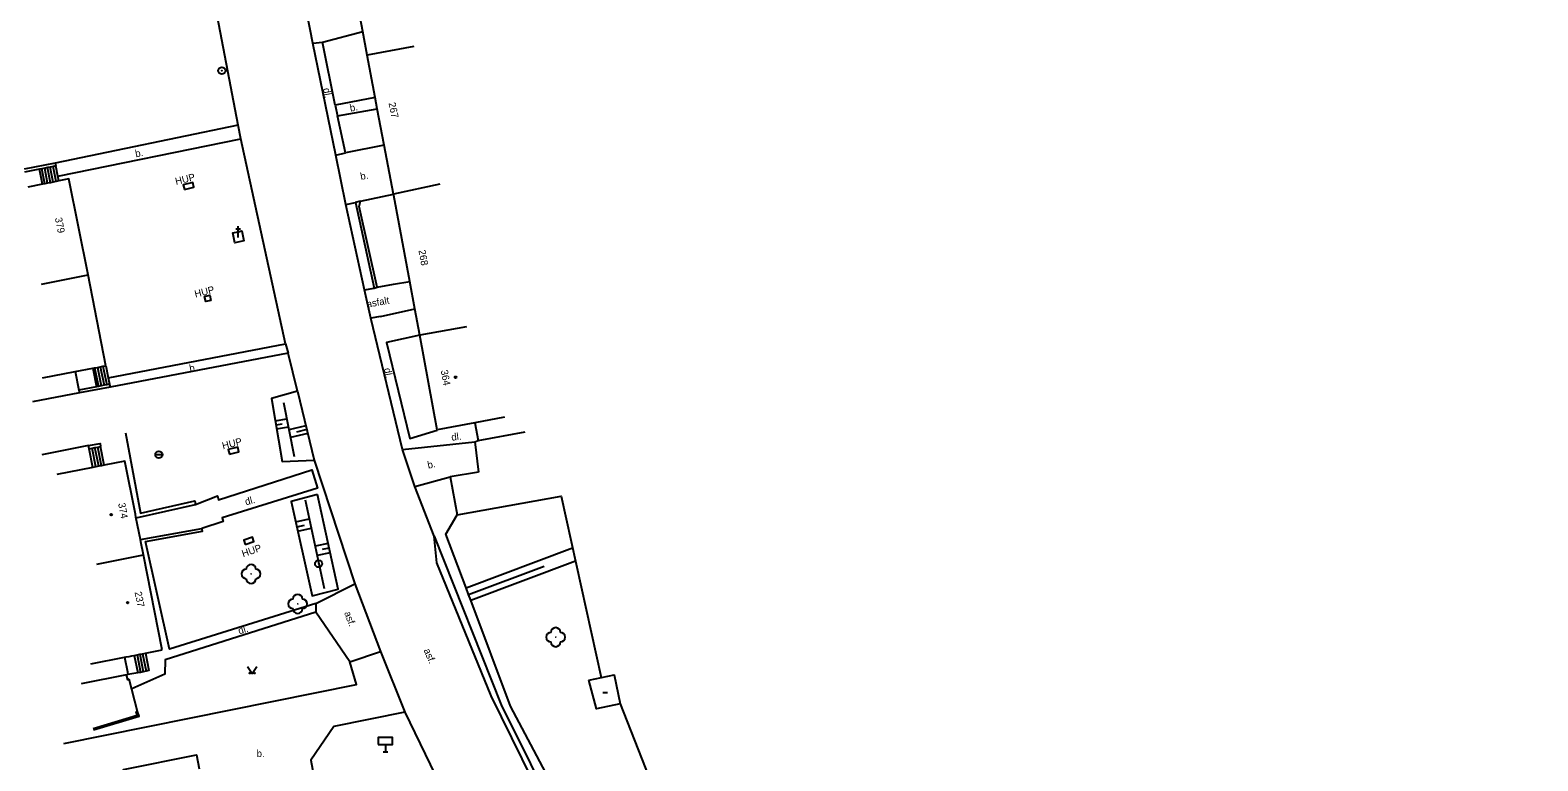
# Model space of a CAD drawing. Extents: x -582162 to -561283, y -1187583 to -1183539.
# Drawn here: x -578179.7 to -578021.2, y -1186545 to -1186468.2 of the extents above; entities that cross this region are included whole.
import ezdxf

# ---------------------------------------------------------------- set-up
doc = ezdxf.new("R2010")
doc.units = 0
for name, color, linetype in [('Vrstva 1', 7, 'Continuous'), ('Vrstva 10', 7, 'Continuous'), ('Vrstva 11', 7, 'Continuous'), ('Vrstva 12', 7, 'Continuous'), ('Vrstva 14', 7, 'Continuous'), ('Vrstva 3', 7, 'Continuous'), ('Vrstva 4', 7, 'Continuous'), ('Vrstva 6', 7, 'Continuous'), ('Vrstva 8', 7, 'Continuous'), ('Vrstva 9', 7, 'Continuous')]:
    doc.layers.add(name, color=color, linetype=linetype)

# ---------------------------------------------------------------- blocks, each defined once
blk = doc.blocks.new('1.079')
at = {"layer": 'Vrstva 1'}
for radius in [0.75, 0.001]:
    blk.add_circle((0, -0.001), radius, dxfattribs=at)
blk = doc.blocks.new('3.130')
at = {"layer": 'Vrstva 1'}
blk.add_circle((0, 0), 0.001, dxfattribs=at)
for centre, start, end in [((-1, 0), 90, 270), ((0, 1), 0, 180), ((1, 0), 270, 90), ((0, -1), 180, 360)]:
    blk.add_arc(centre, 1, start, end, dxfattribs=at)
blk = doc.blocks.new('3.140')
at = {"layer": 'Vrstva 1'}
blk.add_lwpolyline([(-1, 1.5), (0, 0), (1, 1.5)], dxfattribs=at)
for centre in [(-0.5, 0.1), (0.5, 0.1)]:
    blk.add_circle(centre, 0.1, dxfattribs=at)
blk = doc.blocks.new('4.020')
at = {"layer": 'Vrstva 1'}
blk.add_circle((0, 0), 0.175, dxfattribs=at)
blk = doc.blocks.new('4.030')
at = {"layer": 'Vrstva 1'}
blk.add_line((-0.5, 0), (0.5, 0), dxfattribs=at)
blk = doc.blocks.new('5.261')
at = {"layer": 'Vrstva 1'}
for p, q in [((-0.5, 0), (0.5, 0)), ((0, 1.5), (0, 0))]:
    blk.add_line(p, q, dxfattribs=at)
blk.add_lwpolyline([(-1.5, 1.5), (1.5, 1.5), (1.5, 3), (-1.5, 3)], close=True, dxfattribs=at)
blk = doc.blocks.new('8.110')
at = {"layer": 'Vrstva 1'}
blk.add_line((-0.75, 0), (0.75, 0), dxfattribs=at)
blk.add_circle((0, 0), 0.75, dxfattribs=at)

msp = doc.modelspace()

# ---------------------------------------------------------------- linework, layer by layer
at = {"layer": 'Vrstva 10'}
for points in [[(-578157.78, -1186478.2), (-578162.64, -1186452.9)], [(-578149.96, -1186469.58), (-578150.56, -1186466.51)], [(-578148.93, -1186469.45), (-578144.7, -1186468.33)], [(-578149.96, -1186469.58), (-578148.93, -1186469.45)], [(-578147.54, -1186481.33), (-578149.96, -1186469.58)], [(-578147.59, -1186476.07), (-578148.93, -1186469.45)], [(-578143.39, -1186475.29), (-578147.59, -1186476.07)], [(-578147.59, -1186476.07), (-578147.35, -1186477.22)], [(-578147.35, -1186477.22), (-578143.17, -1186476.47)], [(-578157.78, -1186478.2), (-578177.01, -1186482.17)], [(-578157.5, -1186479.63), (-578157.78, -1186478.2)], [(-578146.51, -1186481.11), (-578147.35, -1186477.22)], [(-578176.73, -1186483.54), (-578157.5, -1186479.63)], [(-578152.83, -1186501.19), (-578157.5, -1186479.63)], [(-578142.45, -1186480.29), (-578146.51, -1186481.11)], [(-578147.54, -1186481.33), (-578146.51, -1186481.11)], [(-578146.47, -1186486.53), (-578147.54, -1186481.33)], [(-578177.01, -1186482.17), (-578180.29, -1186482.83)], [(-578178.66, -1186482.81), (-578180.23, -1186483.12)], [(-578178.42, -1186482.77), (-578178.66, -1186482.81)], [(-578178.34, -1186484.4), (-578178.66, -1186482.81)], [(-578178.12, -1186482.71), (-578178.42, -1186482.77)], [(-578178.1, -1186484.35), (-578178.42, -1186482.77)], [(-578177.83, -1186482.65), (-578178.12, -1186482.71)], [(-578177.81, -1186484.3), (-578178.12, -1186482.71)], [(-578177.54, -1186482.59), (-578177.83, -1186482.65)], [(-578177.51, -1186484.24), (-578177.83, -1186482.65)], [(-578177.24, -1186482.53), (-578177.54, -1186482.59)], [(-578177.22, -1186484.18), (-578177.54, -1186482.59)], [(-578176.95, -1186482.47), (-578177.24, -1186482.53)], [(-578176.92, -1186484.12), (-578177.24, -1186482.53)], [(-578177.01, -1186482.17), (-578176.95, -1186482.47)], [(-578176.73, -1186483.54), (-578176.95, -1186482.47)], [(-578176.63, -1186484.06), (-578176.73, -1186483.54)], [(-578163.44, -1186484.96), (-578162.44, -1186484.71), (-578162.56, -1186484.22), (-578163.56, -1186484.48), (-578163.44, -1186484.96)], [(-578146.47, -1186486.53), (-578145.46, -1186486.33)], [(-578144.52, -1186495.49), (-578146.47, -1186486.53)], [(-578144.93, -1186486.17), (-578145.46, -1186486.33)], [(-578145.46, -1186486.33), (-578143.5, -1186495.32)], [(-578157.79, -1186489.39), (-578157.4, -1186489.31), (-578157.19, -1186490.35), (-578158.15, -1186490.55), (-578158.36, -1186489.5), (-578157.79, -1186489.39)], [(-578158.04, -1186489.09), (-578157.79, -1186489.09)], [(-578157.79, -1186489.09), (-578157.79, -1186488.8)], [(-578157.79, -1186489.39), (-578157.79, -1186489.09)], [(-578157.79, -1186489.09), (-578157.55, -1186489.09)], [(-578157.79, -1186490.01), (-578157.79, -1186489.39)], [(-578160.66, -1186496.62), (-578161.2, -1186496.73), (-578161.32, -1186496.19), (-578160.78, -1186496.07), (-578160.66, -1186496.62)], [(-578144.52, -1186495.49), (-578143.5, -1186495.32)], [(-578143.87, -1186498.48), (-578144.52, -1186495.49)], [(-578143.5, -1186495.32), (-578143.2, -1186495.21)], [(-578141.47, -1186494.92), (-578139.77, -1186494.63)], [(-578142.83, -1186498.29), (-578139.24, -1186497.49)], [(-578142.83, -1186498.29), (-578143.87, -1186498.48)], [(-578001.12, -1186645.68), (-578034.13, -1186631.61), (-578060.86, -1186618.74), (-578080.51, -1186605.65), (-578096.31, -1186591.68), (-578110.71, -1186574.72), (-578121.4, -1186558.13), (-578131.21, -1186538.19), (-578136.91, -1186524.22), (-578137.19, -1186521.4), (-578139.24, -1186516.18), (-578140.52, -1186512.3), (-578143.87, -1186498.48)], [(-578138.72, -1186500.28), (-578142.2, -1186501.05), (-578139.77, -1186511.12), (-578136.88, -1186510.27)], [(-578171.44, -1186504.75), (-578152.83, -1186501.19)], [(-578152.54, -1186502.17), (-578171.24, -1186505.72)], [(-578152.83, -1186501.19), (-578152.54, -1186502.17)], [(-578151.56, -1186506.14), (-578152.54, -1186502.17)], [(-578173.08, -1186503.75), (-578172.68, -1186505.69)], [(-578172.88, -1186503.71), (-578172.48, -1186505.65)], [(-578172.59, -1186503.66), (-578172.19, -1186505.6)], [(-578172.29, -1186503.6), (-578171.89, -1186505.54)], [(-578172, -1186503.54), (-578171.6, -1186505.48)], [(-578171.71, -1186503.48), (-578171.44, -1186504.75)], [(-578172.68, -1186505.69), (-578174.54, -1186506.05)], [(-578172.48, -1186505.65), (-578172.68, -1186505.69)], [(-578172.19, -1186505.6), (-578172.48, -1186505.65)], [(-578171.89, -1186505.54), (-578172.19, -1186505.6)], [(-578171.6, -1186505.48), (-578171.89, -1186505.54)], [(-578171.3, -1186505.42), (-578171.6, -1186505.48)], [(-578171.44, -1186504.75), (-578171.3, -1186505.42)], [(-578171.3, -1186505.42), (-578171.24, -1186505.72)], [(-578171.24, -1186505.72), (-578174.48, -1186506.34)], [(-578151.56, -1186506.14), (-578149.82, -1186513.4), (-578145.54, -1186526.43), (-578142.83, -1186533.53), (-578140.28, -1186539.92), (-578128.02, -1186565.25), (-578116.68, -1186581.84), (-578105.73, -1186594.33), (-578094.04, -1186605.6), (-578079.84, -1186616.52), (-578063.76, -1186626.62), (-578051.68, -1186633.11), (-578004.55, -1186654.1)], [(-578173.52, -1186511.88), (-578172.31, -1186511.65), (-578172.25, -1186511.97)], [(-578172.84, -1186512.09), (-578172.54, -1186512.03)], [(-578172.54, -1186512.03), (-578172.25, -1186511.97)], [(-578172.16, -1186513.99), (-578172.54, -1186512.03)], [(-578171.86, -1186513.93), (-578172.25, -1186511.97)], [(-578169.63, -1186510.54), (-578168.04, -1186518.98), (-578162.35, -1186517.69), (-578162.27, -1186518.07)], [(-578158.71, -1186512.77), (-578157.72, -1186512.52), (-578157.84, -1186512.04), (-578158.84, -1186512.29), (-578158.71, -1186512.77)], [(-578140.52, -1186512.3), (-578132.92, -1186511.47), (-578132.57, -1186511.35)], [(-578173.45, -1186512.21), (-578173.13, -1186512.15)], [(-578173.13, -1186512.15), (-578172.84, -1186512.09)], [(-578172.74, -1186514.11), (-578173.13, -1186512.15)], [(-578172.45, -1186514.05), (-578172.84, -1186512.09)], [(-578162.27, -1186518.07), (-578159.98, -1186517.16), (-578159.86, -1186517.57), (-578150.06, -1186514.44), (-578149.46, -1186516.35), (-578159.48, -1186519.47), (-578159.36, -1186519.87), (-578161.62, -1186520.58)], [(-578139.24, -1186516.18), (-578135.52, -1186515.16)], [(-578168.51, -1186519.49), (-578162.27, -1186518.07)], [(-578168.07, -1186521.74), (-578161.62, -1186520.58)], [(-578167.53, -1186521.96), (-578161.53, -1186520.88), (-578161.62, -1186520.58)], [(-578157.05, -1186522.27), (-578156.13, -1186521.95), (-578156.28, -1186521.5), (-578157.21, -1186521.81), (-578157.05, -1186522.27)], [(-578149.63, -1186528.47), (-578165, -1186533.29), (-578167.53, -1186521.96)], [(-578149.63, -1186528.47), (-578145.54, -1186526.43)], [(-578149.62, -1186529.4), (-578165.47, -1186534.39), (-578165.49, -1186535.9), (-578168.98, -1186537.44)], [(-578149.63, -1186528.47), (-578149.62, -1186529.4)], [(-578146.06, -1186534.62), (-578149.62, -1186529.4)], [(-578146.06, -1186534.62), (-578142.83, -1186533.53)], [(-578176.11, -1186543.19), (-578145.37, -1186536.98), (-578146.06, -1186534.62)], [(-578169.24, -1186536.45), (-578169.38, -1186536.49), (-578169.52, -1186535.97)], [(-578168.36, -1186539.83), (-578169.24, -1186536.45)], [(-578140.28, -1186539.92), (-578147.73, -1186541.4), (-578150.16, -1186544.94), (-578148.15, -1186555.77), (-578150.75, -1186556.41), (-578154.16, -1186557.14)], [(-578169.55, -1186547.43), (-578169.85, -1186545.94), (-578162.18, -1186544.38), (-578161.88, -1186545.86)]]:
    msp.add_lwpolyline(points, dxfattribs=at)
at = {"layer": 'Vrstva 12'}
for points in [[(-578153.89, -1186509.28), (-578152.69, -1186509.08)], [(-578153.81, -1186509.71), (-578153.17, -1186509.6)], [(-578153.75, -1186510.11), (-578152.52, -1186509.9)], [(-578150.69, -1186509.79), (-578152.46, -1186510.21)], [(-578150.59, -1186510.2), (-578151.68, -1186510.47)], [(-578150.49, -1186510.59), (-578152.3, -1186511.02)], [(-578151.75, -1186519.9), (-578150.33, -1186519.58)], [(-578151.63, -1186520.43), (-578150.82, -1186520.25)], [(-578151.53, -1186520.87), (-578150.12, -1186520.55)], [(-578148.33, -1186522.17), (-578149.7, -1186522.47)], [(-578148.12, -1186523.14), (-578149.49, -1186523.44)], [(-578148.23, -1186522.65), (-578148.98, -1186522.82)], [(-578133.85, -1186526.84), (-578122.66, -1186522.62)], [(-578133.58, -1186527.54), (-578125.64, -1186524.55)], [(-578133.36, -1186528.14), (-578122.36, -1186523.99)]]:
    msp.add_lwpolyline(points, dxfattribs=at)
at = {"layer": 'Vrstva 4'}
for points in [[(-578144.7, -1186468.33), (-578145.21, -1186465.59)], [(-578144.23, -1186470.84), (-578144.7, -1186468.33)], [(-578139.32, -1186469.92), (-578144.23, -1186470.84)], [(-578143.39, -1186475.29), (-578144.23, -1186470.84)], [(-578143.17, -1186476.47), (-578143.39, -1186475.29)], [(-578142.45, -1186480.29), (-578143.17, -1186476.47)], [(-578141.48, -1186485.45), (-578142.45, -1186480.29)], [(-578178.34, -1186484.4), (-578179.91, -1186484.72)], [(-578178.1, -1186484.35), (-578178.34, -1186484.4)], [(-578177.81, -1186484.3), (-578178.1, -1186484.35)], [(-578177.51, -1186484.24), (-578177.81, -1186484.3)], [(-578177.22, -1186484.18), (-578177.51, -1186484.24)], [(-578176.92, -1186484.12), (-578177.22, -1186484.18)], [(-578176.63, -1186484.06), (-578176.92, -1186484.12)], [(-578173.56, -1186493.93), (-578175.58, -1186483.85), (-578176.63, -1186484.06)], [(-578136.59, -1186484.4), (-578141.48, -1186485.45)], [(-578141.45, -1186485.59), (-578141.48, -1186485.45)], [(-578139.77, -1186494.63), (-578141.45, -1186485.59)], [(-578178.46, -1186494.91), (-578173.56, -1186493.93)], [(-578171.71, -1186503.48), (-578173.56, -1186493.93)], [(-578139.24, -1186497.49), (-578139.77, -1186494.63)], [(-578138.72, -1186500.28), (-578139.24, -1186497.49)], [(-578133.8, -1186499.38), (-578138.72, -1186500.28)], [(-578136.89, -1186510.21), (-578138.72, -1186500.28)], [(-578178.37, -1186504.77), (-578174.92, -1186504.1)], [(-578174.92, -1186504.1), (-578173.08, -1186503.75)], [(-578174.92, -1186504.1), (-578174.54, -1186506.05)], [(-578173.08, -1186503.75), (-578172.88, -1186503.71)], [(-578172.88, -1186503.71), (-578172.59, -1186503.66)], [(-578172.59, -1186503.66), (-578172.29, -1186503.6)], [(-578172.29, -1186503.6), (-578172, -1186503.54)], [(-578172, -1186503.54), (-578171.71, -1186503.48)], [(-578174.48, -1186506.34), (-578179.39, -1186507.29)], [(-578174.54, -1186506.05), (-578174.48, -1186506.34)], [(-578132.91, -1186509.47), (-578136.89, -1186510.21)], [(-578129.8, -1186508.9), (-578132.91, -1186509.47)], [(-578132.91, -1186509.47), (-578132.57, -1186511.35)], [(-578132.57, -1186511.35), (-578127.65, -1186510.44)], [(-578173.52, -1186511.88), (-578178.42, -1186512.85)], [(-578173.45, -1186512.21), (-578173.52, -1186511.88)], [(-578173.07, -1186514.17), (-578173.45, -1186512.21)], [(-578168.59, -1186519.09), (-578169.69, -1186513.5), (-578171.86, -1186513.93)], [(-578173.07, -1186514.17), (-578176.85, -1186514.92)], [(-578172.74, -1186514.11), (-578173.07, -1186514.17)], [(-578172.45, -1186514.05), (-578172.74, -1186514.11)], [(-578172.16, -1186513.99), (-578172.45, -1186514.05)], [(-578171.86, -1186513.93), (-578172.16, -1186513.99)], [(-578168.53, -1186519.39), (-578168.59, -1186519.09)], [(-578168.07, -1186521.74), (-578168.53, -1186519.39)], [(-578168.02, -1186521.98), (-578168.07, -1186521.74)], [(-578167.75, -1186523.36), (-578168.02, -1186521.98)], [(-578172.65, -1186524.33), (-578167.75, -1186523.36)], [(-578165.78, -1186533.35), (-578167.75, -1186523.36)], [(-578173.26, -1186534.83), (-578169.73, -1186534.13)], [(-578169.73, -1186534.13), (-578169.55, -1186534.1)], [(-578169.73, -1186534.13), (-578169.43, -1186535.65)], [(-578169.55, -1186534.1), (-578169.26, -1186534.04)], [(-578169.26, -1186534.04), (-578168.96, -1186533.98)], [(-578168.96, -1186533.98), (-578168.71, -1186533.94)], [(-578168.71, -1186533.94), (-578168.42, -1186533.88)], [(-578168.42, -1186533.88), (-578168.12, -1186533.82)], [(-578168.12, -1186533.82), (-578167.83, -1186533.76)], [(-578167.83, -1186533.76), (-578167.53, -1186533.7)], [(-578167.53, -1186533.7), (-578165.78, -1186533.35)], [(-578169.43, -1186535.65), (-578169.37, -1186535.94)], [(-578169.52, -1186535.97), (-578174.28, -1186536.91)], [(-578169.37, -1186535.94), (-578169.52, -1186535.97)], [(-578120.93, -1186536.53), (-578118.29, -1186535.98), (-578117.65, -1186539.04), (-578120.14, -1186539.56), (-578120.93, -1186536.53)]]:
    msp.add_lwpolyline(points, dxfattribs=at)
at = {"layer": 'Vrstva 9'}
for points in [[(-578143.2, -1186495.21), (-578145.08, -1186486.75), (-578144.93, -1186486.17)], [(-578144.93, -1186486.17), (-578141.48, -1186485.45)], [(-578143.2, -1186495.21), (-578141.47, -1186494.92)], [(-578151.56, -1186506.14), (-578154.28, -1186506.93), (-578153.17, -1186513.54), (-578149.82, -1186513.4)], [(-578153.03, -1186507.36), (-578151.9, -1186513.01)], [(-578132.92, -1186511.47), (-578132.54, -1186514.68)], [(-578132.54, -1186514.68), (-578135.52, -1186515.16), (-578134.79, -1186519.16)], [(-578149.46, -1186517.03), (-578152.23, -1186517.77), (-578150.01, -1186527.67), (-578147.28, -1186526.98), (-578149.46, -1186517.03)], [(-578150.77, -1186517.58), (-578148.74, -1186526.89)], [(-578134.79, -1186519.16), (-578123.86, -1186517.18), (-578119.66, -1186536.26)], [(-578008.78, -1186631.03), (-578013.35, -1186637.41), (-578033.36, -1186628.89), (-578056.94, -1186618.11), (-578079.37, -1186604.24), (-578094.26, -1186590.82), (-578109.32, -1186573.61), (-578119.34, -1186557.86), (-578129.16, -1186539.28), (-578133.36, -1186528.14), (-578133.58, -1186527.54), (-578133.85, -1186526.84), (-578135.98, -1186521.19), (-578134.79, -1186519.16)], [(-578137.19, -1186521.4), (-578130.17, -1186539.12), (-578120.86, -1186557.81), (-578110.41, -1186574.18), (-578095.97, -1186591.26), (-578080.01, -1186605.19), (-578061.57, -1186617.69), (-578057.83, -1186619.63)], [(-578167.53, -1186533.7), (-578167.17, -1186535.54), (-578167.46, -1186535.6), (-578167.76, -1186535.66), (-578168.05, -1186535.72), (-578168.35, -1186535.78), (-578169.37, -1186535.94)], [(-578168.71, -1186533.94), (-578168.35, -1186535.78)], [(-578168.42, -1186533.88), (-578168.05, -1186535.72)], [(-578168.12, -1186533.82), (-578167.76, -1186535.66)], [(-578167.83, -1186533.76), (-578167.46, -1186535.6)], [(-578173.04, -1186541.64), (-578168.4, -1186540.23), (-578168.51, -1186539.88), (-578168.36, -1186539.83)], [(-578173, -1186541.78), (-578168.21, -1186540.33), (-578168.36, -1186539.83)], [(-578117.65, -1186539.04), (-578110.08, -1186558.31), (-578095.94, -1186579.16), (-578074.31, -1186601.02), (-578052.22, -1186615.5), (-578037.01, -1186623.75), (-578011.99, -1186633.18)]]:
    msp.add_lwpolyline(points, dxfattribs=at)

# ---------------------------------------------------------------- block references
at = {"layer": 'Vrstva 1', "xscale": 0.5, "yscale": 0.5}
for p in [(-578159.51, -1186472.46), (-578149.34, -1186524.3)]:
    msp.add_blockref('1.079', p, dxfattribs=at)
at = {"layer": 'Vrstva 11', "xscale": 0.5, "yscale": 0.5}
for p in [(-578156.44, -1186525.37), (-578151.54, -1186528.52), (-578124.43, -1186532.02)]:
    msp.add_blockref('3.130', p, dxfattribs=at)
at = {"layer": 'Vrstva 3', "xscale": 0.5, "yscale": 0.5}
msp.add_blockref('3.140', (-578156.32, -1186535.84), dxfattribs=at)
at = {"layer": 'Vrstva 8', "xscale": 0.5, "yscale": 0.5}
for name, p in [('4.020', (-578134.95, -1186504.69)), ('4.020', (-578171.13, -1186519.14)), ('4.020', (-578169.4, -1186528.4)), ('4.030', (-578119.22, -1186537.84))]:
    msp.add_blockref(name, p, dxfattribs=at)
at = {"layer": 'Vrstva 9', "xscale": 0.5, "yscale": 0.5}
for name, p in [('8.110', (-578166.12, -1186512.83)), ('5.261', (-578142.32, -1186544.07))]:
    msp.add_blockref(name, p, dxfattribs=at)

# ---------------------------------------------------------------- texts
at = {"layer": 'Vrstva 14'}
for s, rotation, p in [('dl.', 280.74, (-578148.88, -1186474.35)), ('b.', 10.74, (-578145.99, -1186476.77)), ('b.', 10.74, (-578168.54, -1186481.57)), ('HUP', 13.957, (-578164.31, -1186484.48)), ('b.', 10.74, (-578144.89, -1186483.95)), ('HUP', 13.957, (-578162.28, -1186496.32)), ('asfalt', 10.74, (-578144.22, -1186497.39)), ('b.', 10.74, (-578162.85, -1186504.14)), ('dl.', 280.74, (-578142.48, -1186503.79)), ('HUP', 13.957, (-578159.38, -1186512.28)), ('dl.', 6.901, (-578135.35, -1186511.37)), ('b.', 11.776, (-578137.82, -1186514.31)), ('dl.', 15.399, (-578156.97, -1186518.17)), ('HUP', 18.88, (-578157.27, -1186523.62)), ('asf.', 290.556, (-578146.67, -1186529.46)), ('dl.', 16.798, (-578157.67, -1186531.74)), ('asf.', 293.05, (-578138.32, -1186533.39))]:
    msp.add_text(s, height=0.75, rotation=rotation, dxfattribs=at).set_placement(p)
msp.add_text('b.', height=0.75, dxfattribs=at).set_placement((-578155.85, -1186544.62))
at = {"layer": 'Vrstva 6'}
for s, rotation, p in [('267', 282.1, (-578142, -1186475.87)), ('379', 281.346, (-578177.05, -1186487.96)), ('268', 280.556, (-578138.85, -1186491.36)), ('364', 280.453, (-578136.51, -1186503.98)), ('374', 281.041, (-578170.41, -1186517.97)), ('237', 281.255, (-578168.68, -1186527.29))]:
    msp.add_text(s, height=0.75, rotation=rotation, dxfattribs=at).set_placement(p)

doc.saveas('drawing.dxf')
